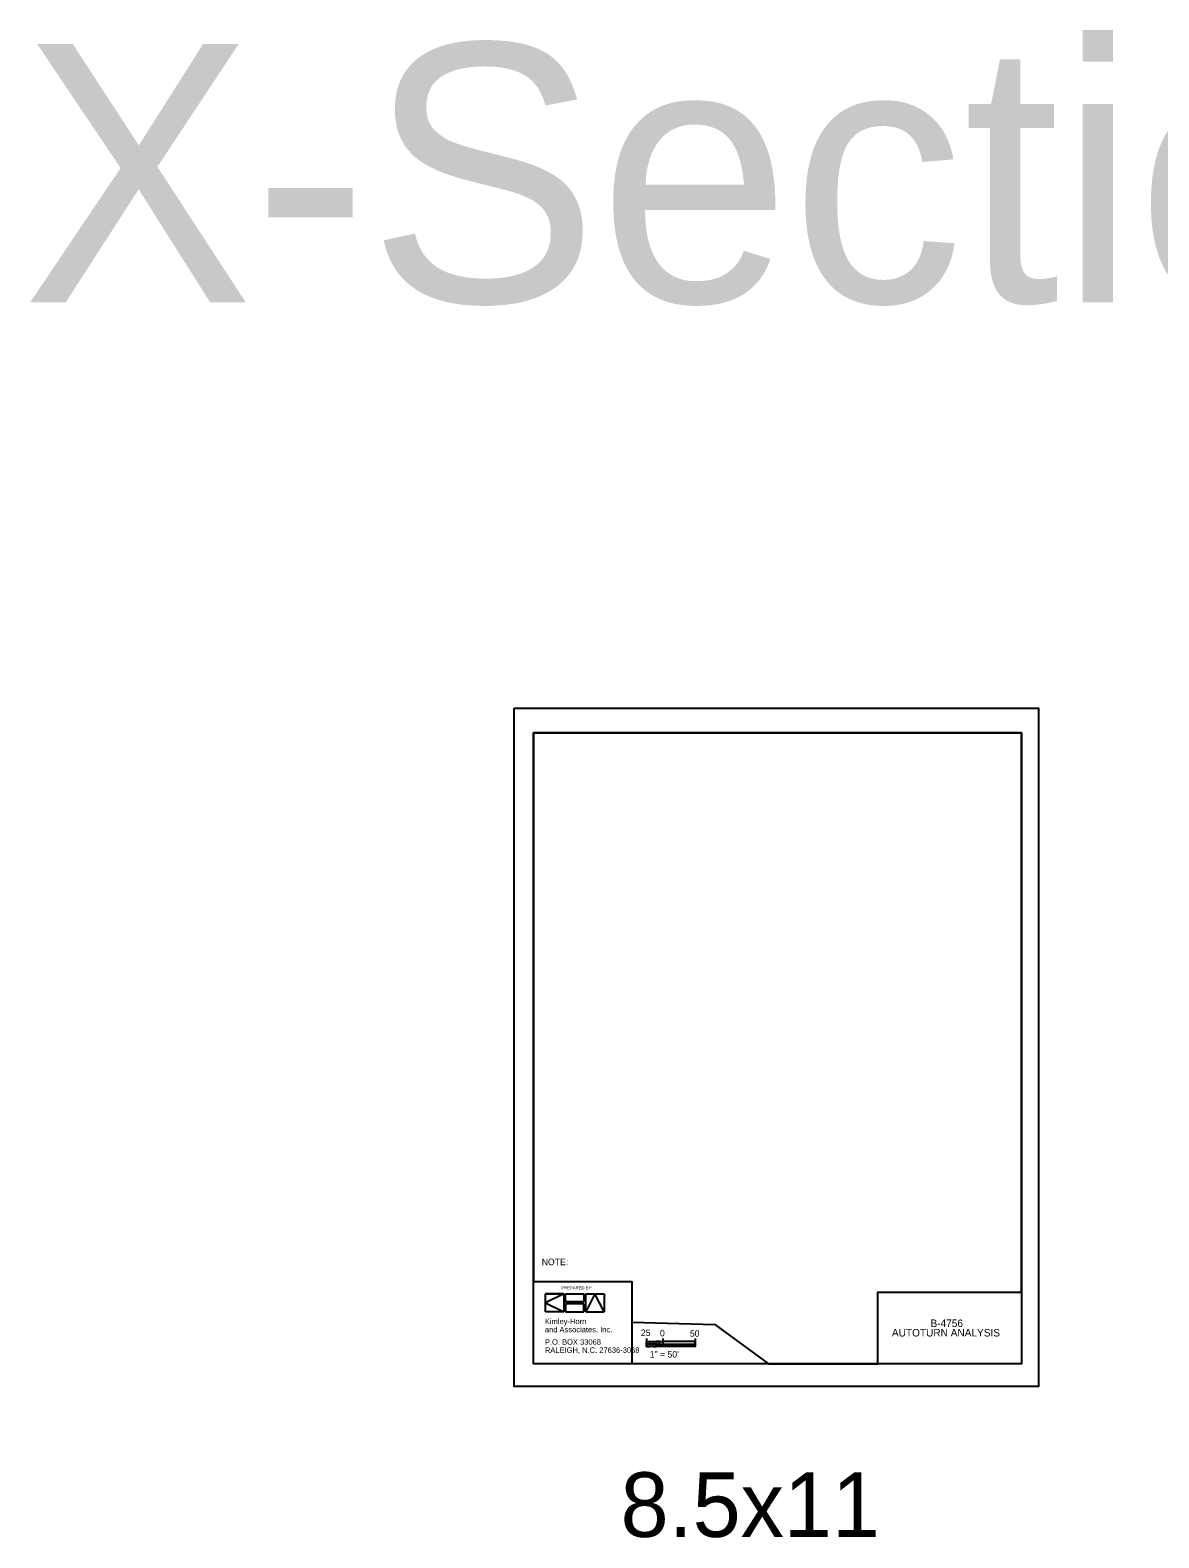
# Model space of a CAD drawing. Extents: x 2431000 to 2534000, y 645879 to 714000.
# Drawn here: x 2461900 to 2464083, y 663062 to 665980 of the extents above; entities that cross this region are included whole.
import ezdxf

# ---------------------------------------------------------------- set-up
doc = ezdxf.new("R2010")
doc.units = 0
for name, color, linetype in [('Level 12', 7, 'Continuous'), ('Level 57', 7, 'Continuous'), ('Level 62', 7, 'Continuous'), ('Scratch_Level_1', 7, 'Continuous'), ('Sheet Plot Border Outside CELL', 7, 'Continuous')]:
    doc.layers.add(name, color=color, linetype=linetype)

msp = doc.modelspace()

# ---------------------------------------------------------------- linework, layer by layer
at = {"layer": 'Level 12'}
for p, q in [((2462896.3, 663534.5), (2462931.6, 663534.5)), ((2462931.6, 663534.5), (2462896.3, 663534.5)), ((2462896.3, 663534.5), (2462931.6, 663534.5)), ((2462931.6, 663534.5), (2462896.3, 663516.8)), ((2462896.3, 663516.8), (2462896.3, 663534.5)), ((2462896.3, 663516.8), (2462931.6, 663499.2)), ((2462896.3, 663499.2), (2462896.3, 663516.8)), ((2462931.6, 663534.5), (2462931.6, 663499.2)), ((2462935.3, 663518.8), (2462935.3, 663534.5)), ((2462935.3, 663534.5), (2462970.7, 663534.5)), ((2462970.7, 663518.8), (2462935.3, 663518.8)), ((2462970.7, 663514.7), (2462935.3, 663514.7)), ((2462935.3, 663514.7), (2462935.3, 663499.2)), ((2462970.7, 663534.5), (2462970.7, 663518.8)), ((2462970.7, 663499.2), (2462970.7, 663514.7)), ((2462974.6, 663499.2), (2462974.6, 663534.5)), ((2462974.6, 663534.5), (2462992.2, 663534.5)), ((2462992.2, 663534.5), (2462974.6, 663499.2)), ((2463009.9, 663499.2), (2462992.2, 663534.5)), ((2462992.2, 663534.5), (2463009.9, 663534.5)), ((2463009.9, 663534.5), (2463009.9, 663499.2)), ((2462931.6, 663499.2), (2462896.3, 663499.2)), ((2462935.3, 663499.2), (2462970.7, 663499.2)), ((2462974.6, 663499.2), (2463009.9, 663499.2)), ((2463092, 663447.7), (2463092, 663441.9)), ((2463123.3, 663447.7), (2463123.3, 663441.9))]:
    msp.add_line(p, q, dxfattribs=at)
msp.add_lwpolyline([(2463185.8, 663447.7), (2463185.8, 663432.5), (2463092, 663432.5), (2463092, 663441.9), (2463123.3, 663441.9)], dxfattribs=at)
for points in [[(2463098.3, 663437.2), (2463092, 663437.2), (2463092, 663432.5), (2463098.3, 663432.5)], [(2463104.5, 663437.2), (2463098.3, 663437.2), (2463098.3, 663441.9), (2463104.5, 663441.9)], [(2463110.8, 663437.2), (2463104.5, 663437.2), (2463104.5, 663432.5), (2463110.8, 663432.5)], [(2463117, 663441.9), (2463110.8, 663441.9), (2463110.8, 663437.2), (2463117, 663437.2)], [(2463123.3, 663432.5), (2463117, 663432.5), (2463117, 663437.2), (2463123.3, 663437.2)], [(2463185.8, 663441.9), (2463123.3, 663441.9), (2463123.3, 663437.2), (2463185.8, 663437.2)]]:
    msp.add_lwpolyline(points, close=True, dxfattribs=at)
at = {"layer": 'Level 57'}
for points in [[(2462873.3, 664620.1), (2463817, 664620.1), (2463817, 663398.9), (2462873.3, 663398.9)], [(2463063.6, 663398.9), (2462873.3, 663398.9), (2462873.3, 663558.2), (2463063.6, 663558.2)], [(2463817, 663398.9), (2463539.4, 663398.9), (2463539.4, 663537.6), (2463817, 663537.6)]]:
    msp.add_lwpolyline(points, close=True, dxfattribs=at)
at = {"layer": 'Level 62'}
for p, q in [((2462835.6, 664667.8), (2462835.6, 664667.8)), ((2463850.3, 663354.7), (2463850.3, 663354.7))]:
    msp.add_line(p, q, dxfattribs=at)
at = {"layer": 'Sheet Plot Border Outside CELL'}
for points in [[(2462835.6, 664667.8), (2463850.3, 664667.8), (2463850.3, 663354.7), (2462835.6, 663354.7)], [(2462873.3, 663558.2), (2463063.6, 663558.2), (2463063.6, 663479.7), (2463224.1, 663474.7), (2463327.6, 663398.9), (2463539.4, 663398.9), (2463539.4, 663537.6), (2463817, 663537.6), (2463817, 664620.1), (2462873.3, 664620.1)], [(2462873.3, 663558.2), (2463063.6, 663558.2), (2463063.6, 663479.7), (2463224.1, 663474.7), (2463327.6, 663398.9), (2463539.4, 663398.9), (2463539.4, 663537.6), (2463817, 663537.6), (2463817, 664620.1), (2462873.3, 664620.1)], [(2462873.3, 663558.2), (2463063.6, 663558.2), (2463063.6, 663479.7), (2463224.1, 663474.7), (2463327.6, 663398.9), (2463539.4, 663398.9), (2463539.4, 663537.6), (2463817, 663537.6), (2463817, 664620.1), (2462873.3, 664620.1)], [(2462873.3, 663558.2), (2463063.6, 663558.2), (2463063.6, 663479.7), (2463224.1, 663474.7), (2463327.6, 663398.9), (2463539.4, 663398.9), (2463539.4, 663537.6), (2463817, 663537.6), (2463817, 664620.1), (2462873.3, 664620.1)], [(2462873.3, 663558.2), (2463063.6, 663558.2), (2463063.6, 663479.7), (2463224.1, 663474.7), (2463327.6, 663398.9), (2463539.4, 663398.9), (2463539.4, 663537.6), (2463817, 663537.6), (2463817, 664620.1), (2462873.3, 664620.1)], [(2462873.3, 663558.2), (2463063.6, 663558.2), (2463063.6, 663479.7), (2463224.1, 663474.7), (2463327.6, 663398.9), (2463539.4, 663398.9), (2463539.4, 663537.6), (2463817, 663537.6), (2463817, 664620.1), (2462873.3, 664620.1)], [(2462873.3, 663558.2), (2463063.6, 663558.2), (2463063.6, 663479.7), (2463224.1, 663474.7), (2463327.6, 663398.9), (2463539.4, 663398.9), (2463539.4, 663537.6), (2463817, 663537.6), (2463817, 664620.1), (2462873.3, 664620.1)], [(2462873.3, 663558.2), (2463063.6, 663558.2), (2463063.6, 663479.7), (2463224.1, 663474.7), (2463327.6, 663398.9), (2463539.4, 663398.9), (2463539.4, 663537.6), (2463817, 663537.6), (2463817, 664620.1), (2462873.3, 664620.1)], [(2462873.3, 663558.2), (2463063.6, 663558.2), (2463063.6, 663479.7), (2463224.1, 663474.7), (2463327.6, 663398.9), (2463539.4, 663398.9), (2463539.4, 663537.6), (2463817, 663537.6), (2463817, 664620.1), (2462873.3, 664620.1)], [(2462873.3, 663558.2), (2463063.6, 663558.2), (2463063.6, 663479.7), (2463224.1, 663474.7), (2463327.6, 663398.9), (2463539.4, 663398.9), (2463539.4, 663537.6), (2463817, 663537.6), (2463817, 664620.1), (2462873.3, 664620.1)], [(2462873.3, 663558.2), (2463063.6, 663558.2), (2463063.6, 663479.7), (2463224.1, 663474.7), (2463327.6, 663398.9), (2463539.4, 663398.9), (2463539.4, 663537.6), (2463817, 663537.6), (2463817, 664620.1), (2462873.3, 664620.1)], [(2462873.3, 663558.2), (2463063.6, 663558.2), (2463063.6, 663479.7), (2463224.1, 663474.7), (2463327.6, 663398.9), (2463539.4, 663398.9), (2463539.4, 663537.6), (2463817, 663537.6), (2463817, 664620.1), (2462873.3, 664620.1)], [(2462873.3, 663558.2), (2463063.6, 663558.2), (2463063.6, 663479.7), (2463224.1, 663474.7), (2463327.6, 663398.9), (2463539.4, 663398.9), (2463539.4, 663537.6), (2463817, 663537.6), (2463817, 664620.1), (2462873.3, 664620.1)], [(2462873.3, 663558.2), (2463063.6, 663558.2), (2463063.6, 663479.7), (2463224.1, 663474.7), (2463327.6, 663398.9), (2463539.4, 663398.9), (2463539.4, 663537.6), (2463817, 663537.6), (2463817, 664620.1), (2462873.3, 664620.1)], [(2462873.3, 663558.2), (2463063.6, 663558.2), (2463063.6, 663479.7), (2463224.1, 663474.7), (2463327.6, 663398.9), (2463539.4, 663398.9), (2463539.4, 663537.6), (2463817, 663537.6), (2463817, 664620.1), (2462873.3, 664620.1)], [(2462873.3, 663558.2), (2463063.6, 663558.2), (2463063.6, 663479.7), (2463224.1, 663474.7), (2463327.6, 663398.9), (2463539.4, 663398.9), (2463539.4, 663537.6), (2463817, 663537.6), (2463817, 664620.1), (2462873.3, 664620.1)], [(2462873.3, 663558.2), (2463063.6, 663558.2), (2463063.6, 663479.7), (2463224.1, 663474.7), (2463327.6, 663398.9), (2463539.4, 663398.9), (2463539.4, 663537.6), (2463817, 663537.6), (2463817, 664620.1), (2462873.3, 664620.1)], [(2462873.3, 663558.2), (2463063.6, 663558.2), (2463063.6, 663479.7), (2463224.1, 663474.7), (2463327.6, 663398.9), (2463539.4, 663398.9), (2463539.4, 663537.6), (2463817, 663537.6), (2463817, 664620.1), (2462873.3, 664620.1)], [(2462873.3, 663558.2), (2463063.6, 663558.2), (2463063.6, 663479.7), (2463224.1, 663474.7), (2463327.6, 663398.9), (2463539.4, 663398.9), (2463539.4, 663537.6), (2463817, 663537.6), (2463817, 664620.1), (2462873.3, 664620.1)], [(2462873.3, 663558.2), (2463063.6, 663558.2), (2463063.6, 663479.7), (2463224.1, 663474.7), (2463327.6, 663398.9), (2463539.4, 663398.9), (2463539.4, 663537.6), (2463817, 663537.6), (2463817, 664620.1), (2462873.3, 664620.1)], [(2462873.3, 663558.2), (2463063.6, 663558.2), (2463063.6, 663479.7), (2463224.1, 663474.7), (2463327.6, 663398.9), (2463539.4, 663398.9), (2463539.4, 663537.6), (2463817, 663537.6), (2463817, 664620.1), (2462873.3, 664620.1)], [(2462873.3, 663558.2), (2463063.6, 663558.2), (2463063.6, 663479.7), (2463224.1, 663474.7), (2463327.6, 663398.9), (2463539.4, 663398.9), (2463539.4, 663537.6), (2463817, 663537.6), (2463817, 664620.1), (2462873.3, 664620.1)], [(2462873.3, 663558.2), (2463063.6, 663558.2), (2463063.6, 663479.7), (2463224.1, 663474.7), (2463327.6, 663398.9), (2463539.4, 663398.9), (2463539.4, 663537.6), (2463817, 663537.6), (2463817, 664620.1), (2462873.3, 664620.1)], [(2462873.3, 663558.2), (2463063.6, 663558.2), (2463063.6, 663479.7), (2463224.1, 663474.7), (2463327.6, 663398.9), (2463539.4, 663398.9), (2463539.4, 663537.6), (2463817, 663537.6), (2463817, 664620.1), (2462873.3, 664620.1)], [(2462873.3, 663558.2), (2463063.6, 663558.2), (2463063.6, 663479.7), (2463224.1, 663474.7), (2463327.6, 663398.9), (2463539.4, 663398.9), (2463539.4, 663537.6), (2463817, 663537.6), (2463817, 664620.1), (2462873.3, 664620.1)], [(2462873.3, 663558.2), (2463063.6, 663558.2), (2463063.6, 663479.7), (2463224.1, 663474.7), (2463327.6, 663398.9), (2463539.4, 663398.9), (2463539.4, 663537.6), (2463817, 663537.6), (2463817, 664620.1), (2462873.3, 664620.1)], [(2462873.3, 663558.2), (2463063.6, 663558.2), (2463063.6, 663479.7), (2463224.1, 663474.7), (2463327.6, 663398.9), (2463539.4, 663398.9), (2463539.4, 663537.6), (2463817, 663537.6), (2463817, 664620.1), (2462873.3, 664620.1)], [(2462873.3, 663558.2), (2463063.6, 663558.2), (2463063.6, 663479.7), (2463224.1, 663474.7), (2463327.6, 663398.9), (2463539.4, 663398.9), (2463539.4, 663537.6), (2463817, 663537.6), (2463817, 664620.1), (2462873.3, 664620.1)], [(2462873.3, 663558.2), (2463063.6, 663558.2), (2463063.6, 663479.7), (2463224.1, 663474.7), (2463327.6, 663398.9), (2463539.4, 663398.9), (2463539.4, 663537.6), (2463817, 663537.6), (2463817, 664620.1), (2462873.3, 664620.1)], [(2462873.3, 663558.2), (2463063.6, 663558.2), (2463063.6, 663479.7), (2463224.1, 663474.7), (2463327.6, 663398.9), (2463539.4, 663398.9), (2463539.4, 663537.6), (2463817, 663537.6), (2463817, 664620.1), (2462873.3, 664620.1)], [(2462873.3, 663558.2), (2463063.6, 663558.2), (2463063.6, 663479.7), (2463224.1, 663474.7), (2463327.6, 663398.9), (2463539.4, 663398.9), (2463539.4, 663537.6), (2463817, 663537.6), (2463817, 664620.1), (2462873.3, 664620.1)], [(2462873.3, 663558.2), (2463063.6, 663558.2), (2463063.6, 663479.7), (2463224.1, 663474.7), (2463327.6, 663398.9), (2463539.4, 663398.9), (2463539.4, 663537.6), (2463817, 663537.6), (2463817, 664620.1), (2462873.3, 664620.1)], [(2462873.3, 663558.2), (2463063.6, 663558.2), (2463063.6, 663479.7), (2463224.1, 663474.7), (2463327.6, 663398.9), (2463539.4, 663398.9), (2463539.4, 663537.6), (2463817, 663537.6), (2463817, 664620.1), (2462873.3, 664620.1)], [(2462873.3, 663558.2), (2463063.6, 663558.2), (2463063.6, 663479.7), (2463224.1, 663474.7), (2463327.6, 663398.9), (2463539.4, 663398.9), (2463539.4, 663537.6), (2463817, 663537.6), (2463817, 664620.1), (2462873.3, 664620.1)], [(2462873.3, 663558.2), (2463063.6, 663558.2), (2463063.6, 663479.7), (2463224.1, 663474.7), (2463327.6, 663398.9), (2463539.4, 663398.9), (2463539.4, 663537.6), (2463817, 663537.6), (2463817, 664620.1), (2462873.3, 664620.1)], [(2462873.3, 663558.2), (2463063.6, 663558.2), (2463063.6, 663479.7), (2463224.1, 663474.7), (2463327.6, 663398.9), (2463539.4, 663398.9), (2463539.4, 663537.6), (2463817, 663537.6), (2463817, 664620.1), (2462873.3, 664620.1)], [(2462873.3, 663558.2), (2463063.6, 663558.2), (2463063.6, 663479.7), (2463224.1, 663474.7), (2463327.6, 663398.9), (2463539.4, 663398.9), (2463539.4, 663537.6), (2463817, 663537.6), (2463817, 664620.1), (2462873.3, 664620.1)], [(2462873.3, 663558.2), (2463063.6, 663558.2), (2463063.6, 663479.7), (2463224.1, 663474.7), (2463327.6, 663398.9), (2463539.4, 663398.9), (2463539.4, 663537.6), (2463817, 663537.6), (2463817, 664620.1), (2462873.3, 664620.1)], [(2462873.3, 663558.2), (2463063.6, 663558.2), (2463063.6, 663479.7), (2463224.1, 663474.7), (2463327.6, 663398.9), (2463539.4, 663398.9), (2463539.4, 663537.6), (2463817, 663537.6), (2463817, 664620.1), (2462873.3, 664620.1)], [(2462873.3, 663558.2), (2463063.6, 663558.2), (2463063.6, 663479.7), (2463224.1, 663474.7), (2463327.6, 663398.9), (2463539.4, 663398.9), (2463539.4, 663537.6), (2463817, 663537.6), (2463817, 664620.1), (2462873.3, 664620.1)], [(2462873.3, 663558.2), (2463063.6, 663558.2), (2463063.6, 663479.7), (2463224.1, 663474.7), (2463327.6, 663398.9), (2463539.4, 663398.9), (2463539.4, 663537.6), (2463817, 663537.6), (2463817, 664620.1), (2462873.3, 664620.1)]]:
    msp.add_lwpolyline(points, close=True, dxfattribs=at)

# ---------------------------------------------------------------- texts
at = {"layer": 'Level 12'}
for s, height, p in [('NOTE:  ', 12.5, (2462889.2, 663589.8)), ('PREPARED BY:', 5.933, (2462926.8, 663542.9)), ('Kimley-Horn', 10.547, (2462895.3, 663475.8)), ('B-4756', 14.58, (2463641.2, 663470.1)), ('and Associates, Inc.', 10.547, (2462895.3, 663459.9)), ('25', 12.5, (2463081.1, 663452.8)), ('0', 12.5, (2463117.9, 663452.1)), ('50', 12.5, (2463175.8, 663451.4)), ('AUTOTURN ANALYSIS', 14.583, (2463566.6, 663451.8)), ('P.O. BOX 33068', 10.547, (2462895.3, 663435.9)), ('RALEIGH, N.C. 27636-3068', 10.547, (2462895.3, 663420.1)), ('1" = 50\'', 12.5, (2463098.1, 663411))]:
    msp.add_text(s, height=height, rotation=360, dxfattribs=at).set_placement(p)
at = {"layer": 'Scratch_Level_1'}
for s, height, p in [('X-Section Sheet Border', 499.999, (2461884.5, 665453.2)), ('8.5x11', 125, (2463041.7, 663063.9))]:
    msp.add_text(s, height=height, dxfattribs=at).set_placement(p)

doc.saveas('drawing.dxf')
